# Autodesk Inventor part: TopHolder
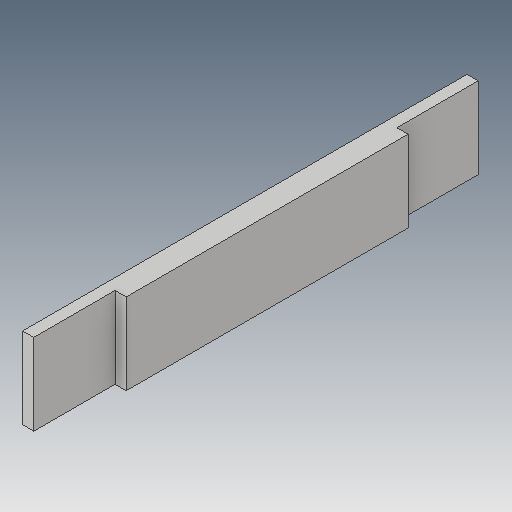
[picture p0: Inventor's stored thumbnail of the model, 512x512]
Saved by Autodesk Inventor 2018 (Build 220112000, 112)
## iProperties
Created: 2018-05
Part Number: TopHolder
Material: Generic
Document SubType Name: Modeling
Designer: arivu
Density: 1 g/cm^3
Appearance: Default
Author: arivu
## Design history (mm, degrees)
derived "WaterTank.ipt"
feature "Solid62::WaterTank.ipt" dims "d0" = 10
tag "TaggingFeature1"
body "Solid1"
